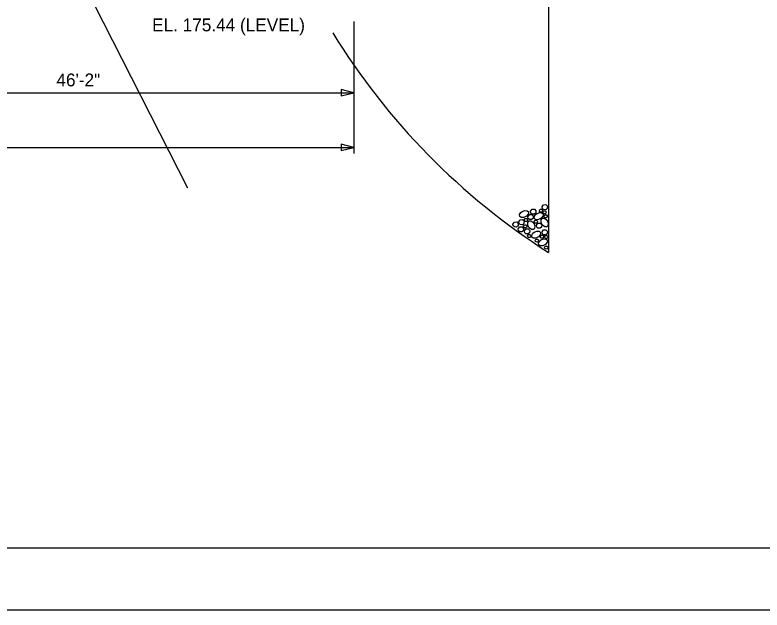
# Model space of a CAD drawing. Extents: x -20 to 509, y -659 to 21.
# Drawn here: x 139.4 to 197.5, y -176.3 to -130 of the extents above; entities that cross this region are included whole.
import ezdxf

# ---------------------------------------------------------------- set-up
doc = ezdxf.new("R2010")
doc.units = 0
for name, color, linetype in [('Arrowhead Terminators CELL', 7, 'Continuous'), ('Auto Dimensioning', 7, 'Continuous'), ('Dimension Lines', 7, 'Continuous'), ('Exist Hydro Stream or Body of Water', 7, 'Continuous'), ('Miscellaneous Lines CELL', 7, 'Continuous'), ('Plan Sheet CELL', 7, 'Continuous'), ('Plot Shape CELL', 7, 'Continuous'), ('Sub End Bent Cap Lines CELL', 7, 'Continuous'), ('Sup Concrete Girder Lines', 7, 'Continuous'), ('Text', 7, 'Continuous')]:
    doc.layers.add(name, color=color, linetype=linetype)

# ---------------------------------------------------------------- blocks, each defined once
blk = doc.blocks.new('AH')
at = {"layer": 'Sub End Bent Cap Lines CELL'}
blk.add_lwpolyline([(0, 0), (-1.25, 0.312), (-1.25, -0.312)], close=True, dxfattribs=at)

msp = doc.modelspace()

# ---------------------------------------------------------------- linework, layer by layer
at = {"layer": 'Arrowhead Terminators CELL'}
msp.add_lwpolyline([(165.739, -136.045), (164.739, -135.795), (164.739, -136.295)], close=True, dxfattribs=at)
at = {"layer": 'Auto Dimensioning'}
for p, q in [((165.739, -130.492), (165.739, -140.762)), ((119.574, -136.045), (165.739, -136.045)), ((73.409, -140.297), (165.739, -140.297))]:
    msp.add_line(p, q, dxfattribs=at)
at = {"layer": 'Exist Hydro Stream or Body of Water'}
msp.add_lwpolyline([(152.818, -143.472), (145.52, -129.155), (141.407, -120.782), (140.558, -120.72), (140.462, -115.767), (134.29, -102.218)], dxfattribs=at)
at = {"layer": 'Miscellaneous Lines CELL'}
for points in [[(180.382, -144.921), (180.494, -144.762), (180.673, -144.752), (180.798, -144.881), (180.78, -145.061), (180.669, -145.153), (180.492, -145.141), (180.409, -145.06), (180.382, -144.921)], [(178.827, -145.286), (179.037, -145.203), (179.229, -145.22), (179.321, -145.307), (179.318, -145.463), (179.179, -145.641), (178.964, -145.748), (178.762, -145.752), (178.648, -145.671), (178.637, -145.51), (178.73, -145.365), (178.835, -145.281)], [(179.491, -145.266), (179.603, -145.107), (179.782, -145.096), (179.906, -145.225), (179.888, -145.406), (179.778, -145.498), (179.601, -145.485), (179.518, -145.405), (179.491, -145.266)], [(180.171, -145.2), (180.238, -145.105), (180.345, -145.099), (180.42, -145.176), (180.409, -145.284), (180.343, -145.34), (180.237, -145.332), (180.187, -145.284), (180.171, -145.2)], [(180.441, -145.324), (180.508, -145.228), (180.616, -145.222), (180.69, -145.299), (180.68, -145.408), (180.613, -145.463), (180.507, -145.455), (180.457, -145.407), (180.441, -145.324)], [(178.561, -146.088), (178.674, -145.928), (178.852, -145.918), (178.977, -146.047), (178.959, -146.228), (178.848, -146.32), (178.672, -146.307), (178.589, -146.226), (178.562, -146.088)], [(178.995, -145.93), (179.062, -145.834), (179.169, -145.828), (179.244, -145.905), (179.233, -146.014), (179.167, -146.069), (179.061, -146.061), (179.011, -146.013), (178.995, -145.93)], [(179.28, -145.688), (179.392, -145.528), (179.571, -145.518), (179.695, -145.647), (179.677, -145.828), (179.567, -145.92), (179.39, -145.907), (179.307, -145.826), (179.28, -145.688)], [(179.966, -145.456), (180.175, -145.373), (180.368, -145.389), (180.459, -145.476), (180.456, -145.633), (180.318, -145.81), (180.103, -145.918), (179.901, -145.921), (179.787, -145.84), (179.776, -145.679), (179.868, -145.535), (179.974, -145.45)], [(180.768, -145.994), (180.851, -146.204), (180.834, -146.397), (180.747, -146.488), (180.591, -146.485), (180.414, -146.346), (180.306, -146.132), (180.303, -145.929), (180.384, -145.816), (180.545, -145.805), (180.689, -145.897), (180.773, -146.003)], [(180.54, -145.641), (180.607, -145.546), (180.714, -145.54), (180.789, -145.617), (180.778, -145.725), (180.712, -145.781), (180.606, -145.773), (180.556, -145.725), (180.54, -145.641)], [(178.114, -146.263), (178.226, -146.103), (178.405, -146.093), (178.529, -146.222), (178.511, -146.403), (178.401, -146.494), (178.224, -146.482), (178.141, -146.401), (178.114, -146.263)], [(178.53, -146.641), (178.642, -146.482), (178.821, -146.471), (178.945, -146.6), (178.927, -146.781), (178.817, -146.873), (178.64, -146.86), (178.557, -146.78), (178.53, -146.641)], [(178.946, -146.414), (179.014, -146.319), (179.121, -146.312), (179.196, -146.39), (179.185, -146.498), (179.119, -146.553), (179.013, -146.546), (178.963, -146.497), (178.947, -146.414)], [(179.738, -146.2), (179.821, -146.41), (179.804, -146.602), (179.717, -146.694), (179.561, -146.691), (179.383, -146.552), (179.276, -146.337), (179.272, -146.135), (179.353, -146.021), (179.515, -146.01), (179.659, -146.103), (179.743, -146.209)], [(179.763, -146.063), (179.83, -145.967), (179.937, -145.961), (180.012, -146.039), (180.001, -146.147), (179.935, -146.202), (179.829, -146.194), (179.779, -146.146), (179.763, -146.063)], [(179.939, -146.359), (180.051, -146.199), (180.23, -146.189), (180.354, -146.318), (180.336, -146.499), (180.226, -146.591), (180.049, -146.578), (179.966, -146.497), (179.939, -146.359)], [(179.004, -146.799), (179.116, -146.64), (179.294, -146.63), (179.419, -146.759), (179.401, -146.939), (179.29, -147.031), (179.114, -147.018), (179.031, -146.938), (179.004, -146.799)], [(179.254, -147.178), (179.321, -147.082), (179.428, -147.076), (179.503, -147.154), (179.492, -147.262), (179.426, -147.317), (179.32, -147.309), (179.27, -147.261), (179.254, -147.178)], [(179.762, -146.893), (179.972, -146.81), (180.165, -146.826), (180.256, -146.913), (180.253, -147.07), (180.114, -147.247), (179.9, -147.355), (179.697, -147.358), (179.583, -147.277), (179.573, -147.116), (179.665, -146.972), (179.771, -146.888)], [(180.387, -146.878), (180.499, -146.719), (180.678, -146.709), (180.803, -146.838), (180.785, -147.018), (180.674, -147.11), (180.498, -147.097), (180.414, -147.017), (180.387, -146.878)], [(179.844, -147.527), (179.911, -147.431), (180.019, -147.425), (180.093, -147.502), (180.082, -147.611), (180.016, -147.666), (179.91, -147.658), (179.86, -147.61), (179.844, -147.527)], [(180.297, -147.502), (180.507, -147.419), (180.7, -147.435), (180.791, -147.522), (180.788, -147.678), (180.649, -147.856), (180.435, -147.963), (180.232, -147.967), (180.118, -147.886), (180.108, -147.725), (180.2, -147.581), (180.306, -147.496)], [(180.255, -147.218), (180.322, -147.122), (180.429, -147.116), (180.504, -147.194), (180.493, -147.302), (180.427, -147.357), (180.321, -147.349), (180.271, -147.301), (180.255, -147.218)], [(180.569, -147.256), (180.636, -147.161), (180.744, -147.155), (180.818, -147.232), (180.807, -147.34), (180.741, -147.395), (180.635, -147.388), (180.585, -147.339), (180.569, -147.256)], [(180.569, -148.072), (180.636, -147.976), (180.744, -147.97), (180.818, -148.048), (180.807, -148.156), (180.741, -148.211), (180.635, -148.203), (180.585, -148.155), (180.569, -148.072)]]:
    msp.add_lwpolyline(points, dxfattribs=at)
at = {"layer": 'Plan Sheet CELL'}
msp.add_line((8.432, -171.454), (264.435, -171.454), dxfattribs=at)
at = {"layer": 'Plot Shape CELL'}
msp.add_lwpolyline([(0, -0.303), (264.505, -0.303), (264.505, -176.303), (0, -176.303)], close=True, dxfattribs=at)
at = {"layer": 'Sup Concrete Girder Lines'}
msp.add_line((180.87, -122.906), (180.87, -148.463), dxfattribs=at)
msp.add_arc((209.68, -103.401), 53.484, 211.54506, 237.40766, dxfattribs=at)

# ---------------------------------------------------------------- block references
at = {"layer": 'Auto Dimensioning', "xscale": 0.8, "yscale": 0.8000000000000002}
msp.add_blockref('AH', (165.739, -140.297), dxfattribs=at)

# ---------------------------------------------------------------- texts
at = {"layer": 'Dimension Lines'}
msp.add_text('46\'-2"', height=1, dxfattribs=at).set_placement((142.59, -135.545))
at = {"layer": 'Text'}
msp.add_text('EL. 175.44 (LEVEL)', height=1, dxfattribs=at).set_placement((150.034, -131.264))

doc.saveas('drawing.dxf')
